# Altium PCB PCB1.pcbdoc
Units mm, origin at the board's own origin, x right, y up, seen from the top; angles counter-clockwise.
Board outline 185.93 x 117.47 mm, 2 copper layers (Top Layer, Bottom Layer); 11 components, 33 nets, 102 pads, 0 vias.
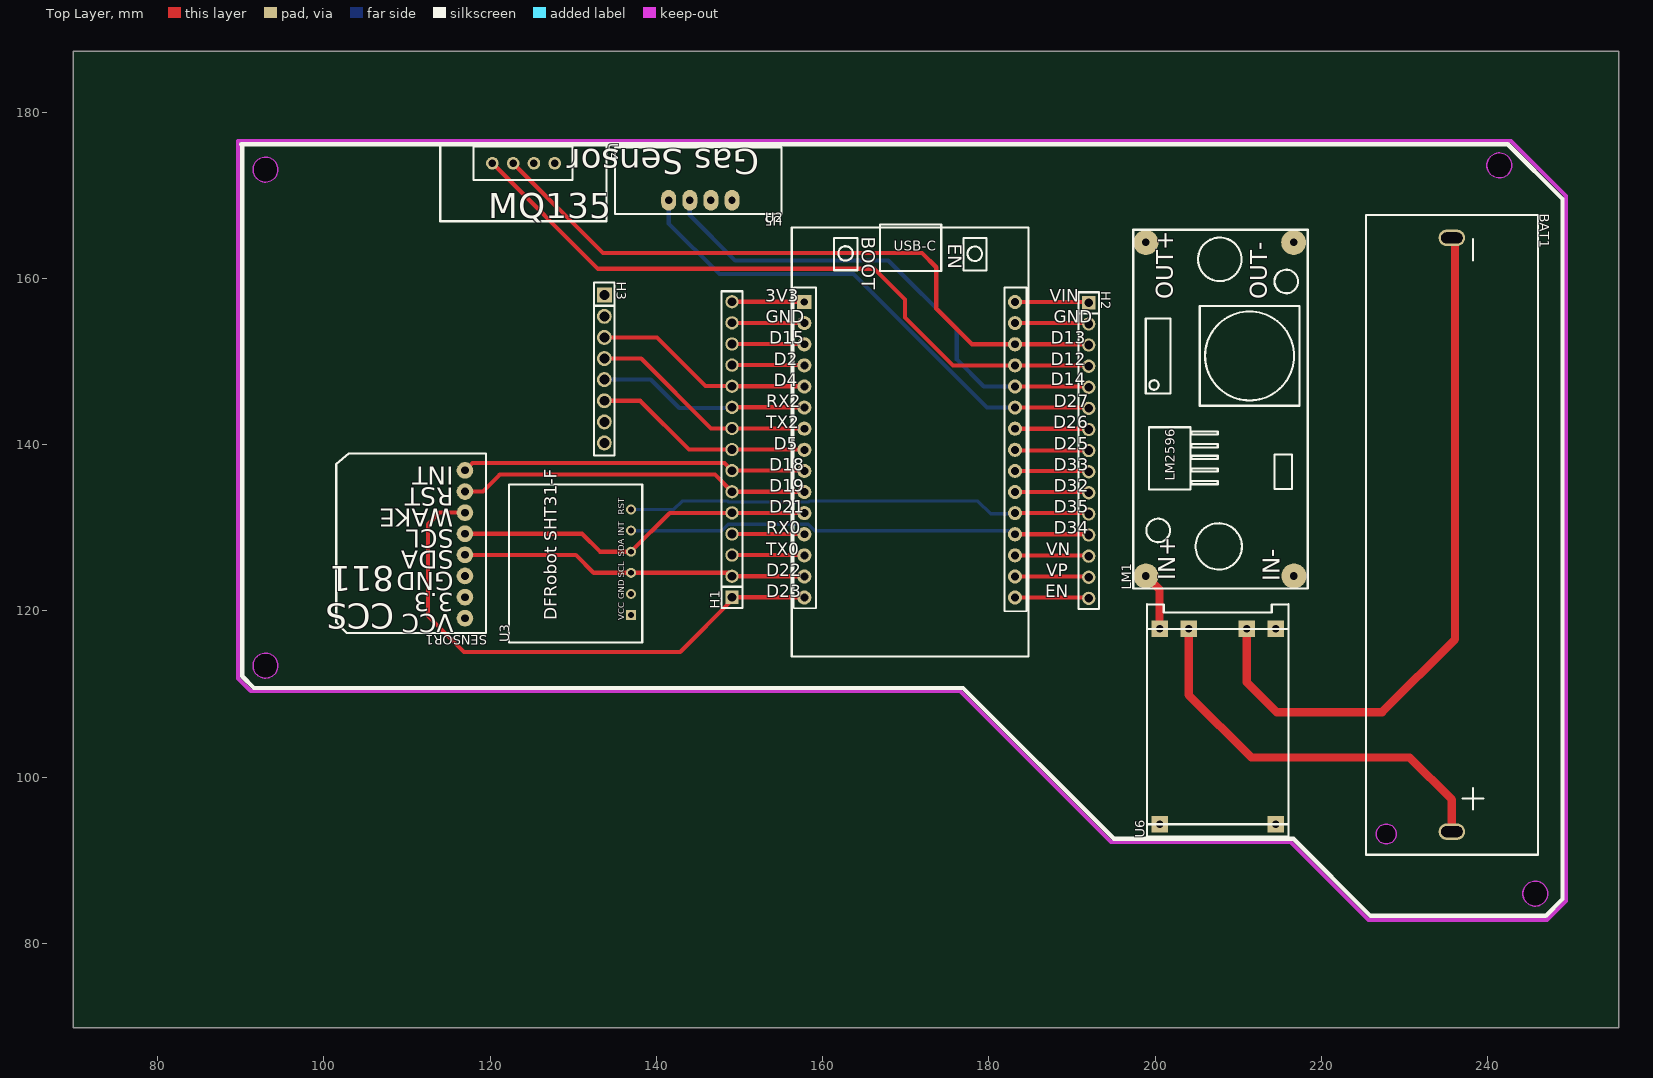
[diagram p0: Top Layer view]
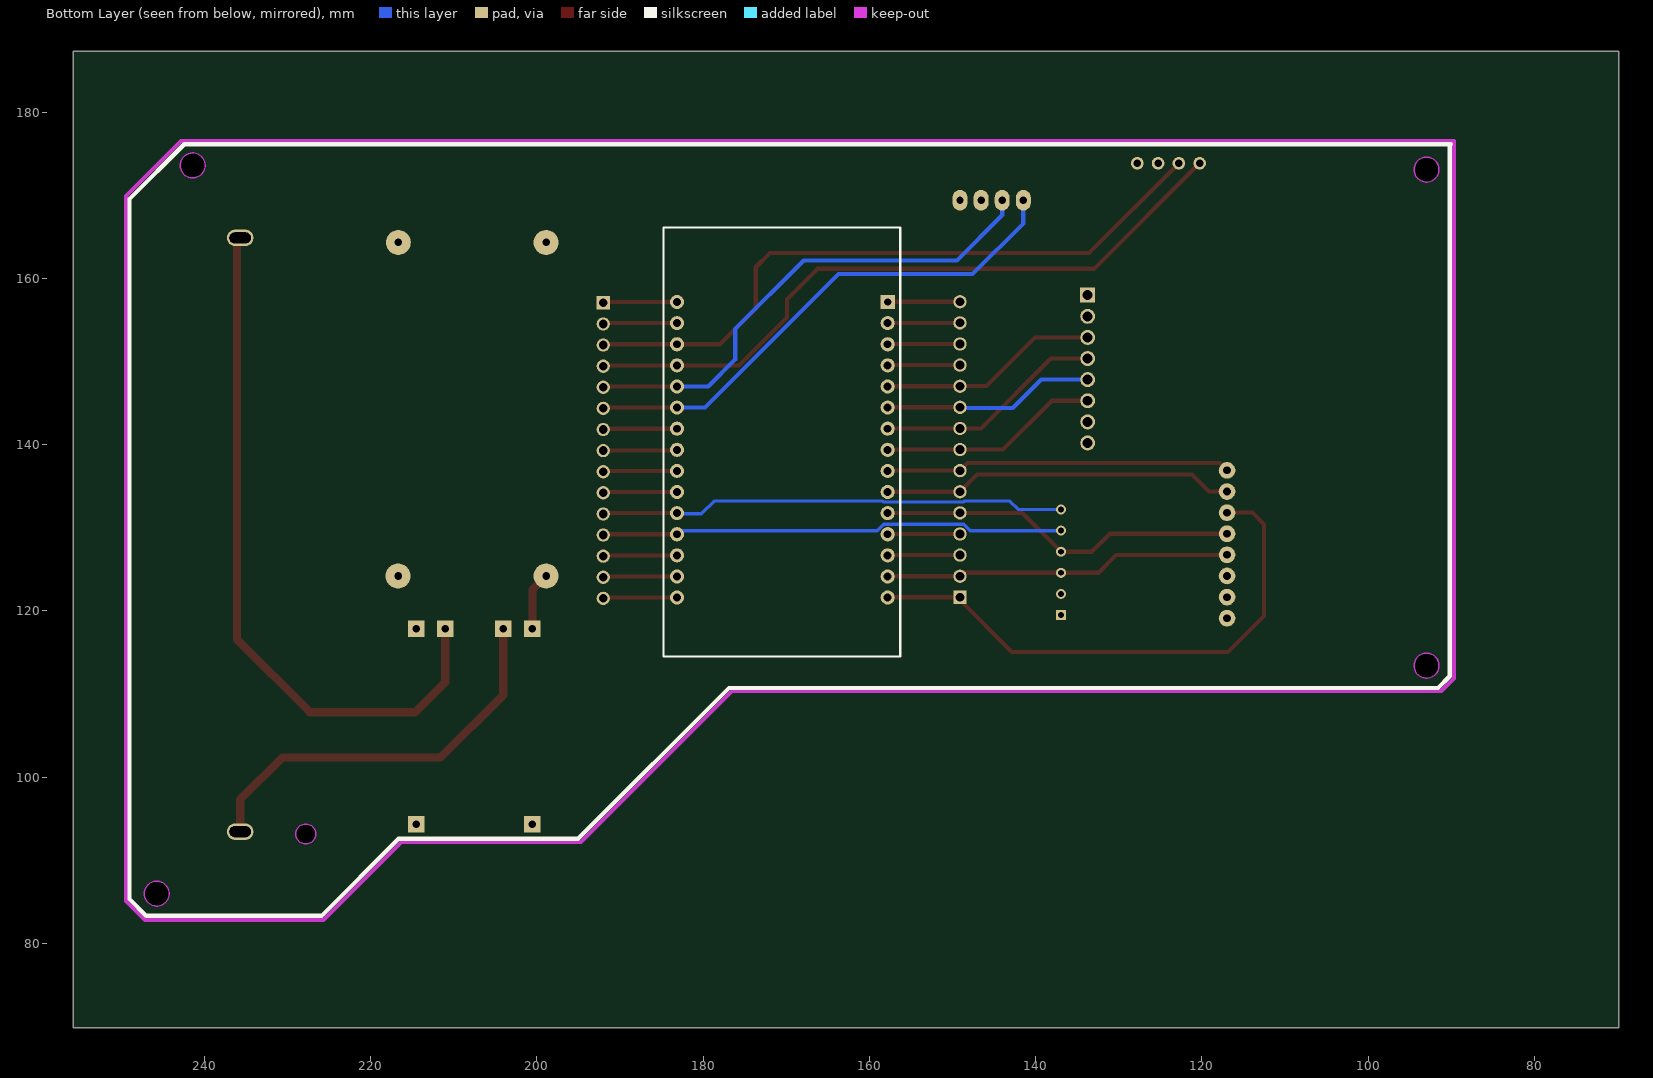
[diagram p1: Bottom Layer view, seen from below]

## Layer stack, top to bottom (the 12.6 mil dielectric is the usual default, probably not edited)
Top Layer: signal copper (thickness not stored)
Dielectric: dielectric 0.32, FR-4, Dk 4.8
Bottom Layer: signal copper (thickness not stored)

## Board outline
255.778,69.85 69.85,69.85 69.85,187.325 255.778,187.325
cut-out: 94.464,173.101 cw(c92.964,173.101) 91.464,173.101 cw(c92.964,173.101)
cut-out: 94.464,113.411 cw(c92.964,113.411) 91.464,113.411 cw(c92.964,113.411)
cut-out: 242.927,173.609 cw(c241.427,173.609) 239.927,173.609 cw(c241.427,173.609)
cut-out: 247.245,85.979 cw(c245.745,85.979) 244.245,85.979 cw(c245.745,85.979)

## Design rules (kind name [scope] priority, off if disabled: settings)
BoardOutlineClearance copperThickness1oz [All] p0: genericclearance=0.254 ignorepadtopadclearanceinfootprint=FALSE except(0: Arc-SplitContinuation Track-SplitContinuation SMDPad-SplitContinuation THPad-SplitContinuation Via-SplitContinuation Fill-SplitContinuation Poly-SplitContinuation Region-SplitContinuation Text-SplitContinuation; 0.152: Track-CutoutEdge SMDPad-CutoutEdge THPad-CutoutEdge Via-CutoutEdge Region-CutoutEdge; 0.3: Track-OutlineEdge SMDPad-OutlineEdge THPad-OutlineEdge Via-OutlineEdge Fill-OutlineEdge Region-OutlineEdge Poly-OutlineEdge Text-OutlineEdge Fill-CutoutEdge)
BoardOutlineClearance copperThickness2oz [All] p0: genericclearance=0.254 ignorepadtopadclearanceinfootprint=FALSE except(0: Arc-SplitContinuation Track-SplitContinuation SMDPad-SplitContinuation THPad-SplitContinuation Via-SplitContinuation Fill-SplitContinuation Poly-SplitContinuation Region-SplitContinuation Text-SplitContinuation; 0.152: Track-CutoutEdge SMDPad-CutoutEdge THPad-CutoutEdge Via-CutoutEdge Region-CutoutEdge; 0.3: Track-OutlineEdge SMDPad-OutlineEdge THPad-OutlineEdge Via-OutlineEdge Fill-OutlineEdge Region-OutlineEdge Poly-OutlineEdge Text-OutlineEdge Fill-CutoutEdge)
Clearance copperThickness1oz [(InNet('$1N893') OR InNet('$1N889') OR InNet('INT_2') OR InNet('SCL') OR InNet('$1N1122') OR InNet('$1N1120') OR InNet('SDA') OR InNet('RST_2') OR InNet('W') OR InNet('RST_1') OR InNet('RX') OR InNet('TX') OR InNet('SET_1') OR InNet('$1N1104') OR InNet('$1N1102') OR InNet('GND') OR InNet('3.3V') OR InNet('$1N1218') OR InNet('$1N1216') OR InNet('D1') OR InNet('A1') OR InNet('D2') OR InNet('A2') OR InNet('$1N1206') OR InNet('$1N1204') OR InNet('$1N1202') OR InNet('$1N1200') OR InNet('RST_3') OR InNet('INT_3') OR InNet('$1N1194') OR InNet('$1N1192') OR InNet('$1N1190') OR InNet('VCC'))] p1: gap=0.178 ignorepadtopadclearanceinfootprint=FALSE except(0.102: Track-Track; 0.152: Track-SMDPad SMDPad-SMDPad Track-THPad SMDPad-THPad THPad-THPad Track-Via SMDPad-Via THPad-Via Via-Via SMDPad-Fill THPad-Fill Via-Fill Fill-Fill Track-Region SMDPad-Region THPad-Region Via-Region Region-Region Track-Poly SMDPad-Poly THPad-Poly Via-Poly Fill-Poly Region-Poly Poly-Poly Track-Text SMDPad-Text THPad-Text Via-Text Fill-Text Region-Text Poly-Text Text-Text; 0.175: Track-Hole SMDPad-Hole THPad-Hole Via-Hole Fill-Hole Region-Hole Poly-Hole Text-Hole Sheet-Hole; 0.3: Track-Fill Fill-Region Track-Sheet SMDPad-Sheet THPad-Sheet Via-Sheet Fill-Sheet Region-Sheet Poly-Sheet Text-Sheet)
Clearance copperThickness2oz [All] p1: gap=0.178 ignorepadtopadclearanceinfootprint=FALSE except(0.152: Track-SMDPad SMDPad-SMDPad Track-THPad SMDPad-THPad THPad-THPad Track-Via SMDPad-Via THPad-Via Via-Via SMDPad-Fill THPad-Fill Via-Fill Fill-Fill Track-Region SMDPad-Region THPad-Region Via-Region Region-Region Track-Poly SMDPad-Poly THPad-Poly Via-Poly Fill-Poly Region-Poly Poly-Poly Track-Text SMDPad-Text THPad-Text Via-Text Fill-Text Region-Text Poly-Text Text-Text; 0.175: Track-Hole SMDPad-Hole THPad-Hole Via-Hole Fill-Hole Region-Hole Poly-Hole Text-Hole Sheet-Hole; 0.203: Track-Track; 0.3: Track-Fill Fill-Region Track-Sheet SMDPad-Sheet THPad-Sheet Via-Sheet Fill-Sheet Region-Sheet Poly-Sheet Text-Sheet)
DiffPairsRouting differentialPair [All] p1: maxuncoupledlength=10 minlimit=6 maxlimit=6 mostfreqgap=6 toplayer_minwidth=5 toplayer_prefwidth=10 toplayer_maxwidth=100 bottomlayer_minwidth=5 bottomlayer_prefwidth=10 bottomlayer_maxwidth=100
PasteMaskExpansion pasteMaskExpansion [All] p1: expansion=0
PlaneConnect innerPlane [All] p1: planeconnectstyle=Relief reliefexpansion=0.508 reliefentries=4 reliefconductorwidth=0.254 reliefairgap=0.254
PolygonConnect copperRegion [All] p1: connectstyle=Direct reliefentries=4 reliefconductorwidth=10 polygonreliefangle="90 Angle" airgapwidth=10
RoutingVias viaSize [All] p1: viastyle="Through Hole" holewidth=12.0078 minholewidth=11.811 maxholewidth=248.0314 width=24.0158 minwidth=19.685 maxwidth=393.7008
SolderMaskExpansion solderMaskExpansion [All] p1: useseparateexpansions=TRUE expansion=2 expansionbottom=2
Width copperThickness1oz [All] p1: maxlimit=100 minlimit=5 preferedwidth=10
Width copperThickness2oz [All] p1: maxlimit=100 minlimit=8 preferedwidth=10

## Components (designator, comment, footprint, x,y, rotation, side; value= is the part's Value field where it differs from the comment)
BAT1 "BH-18650-A6AJ002" BAT-TH_L77.0-W20.7_BH-18650-A6AJ002 235.712,129.159 r270 top
H1 "HDR-M_2.54_1x15P" HDR-TH_15P-P2.54-V-M 149.098,139.418 r90 top
H2 "HDR-M_2.54_1x15P" HDR-TH_15P-P2.54-V-M 192.024,139.291 r270 top
H3 "HDR-F_2.54_1x8P" HDR-TH_8P-P2.54-V-F-1 133.731,149.098 r270 top
LM1 "LM2596" LM2596-STEPDOWN-MODULE 197.376,122.682 r90 top
SENSOR1 "CCS811" CCS811-1 119.507,138.938 r180 top
U2 "ESP32" "ESP32 DOIT DEVKIT V1 mk2" 170.561,139.418 r0 top
U3 "sht31DFBoard" sht31DFBoard 138.557,116.332 r90 top
U4 "MQ135" MQ135 134.112,176.276 r270 top
U5 "gas sensor mq136" "GAS SENSOR" 145.034,175.768 r180 top
U6 "TP4056 Charging Module" "TP4056 Carging Module" 216.045,92.837 r90 top

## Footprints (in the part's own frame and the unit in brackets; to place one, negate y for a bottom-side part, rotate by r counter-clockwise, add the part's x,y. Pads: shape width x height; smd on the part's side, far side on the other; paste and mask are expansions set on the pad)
BAT-TH_L77.0-W20.7_BH-18650-A6AJ002 [mm]
  oval 2x3.2 hole 1.3 slot 2.6 at 90 deg: 1(-35.725,0) 2(35.725,0)
  Board Outline Layer circle w0.005: c36,-7.9 r1.2
  Board Outline Layer region: 36,-6.7 36.52,-6.819 36.938,-7.152 37.17,-7.633 37.17,-8.167 36.938,-8.648 36.52,-8.981 36,-9.1 36,-9.1 35.479,-8.981 35.062,-8.648 34.83,-8.167 34.83,-7.633 35.062,-7.152 35.479,-6.819 36,-6.7
  Multi-Layer board cut-out: 36,-6.7 36.52,-6.819 36.938,-7.152 37.17,-7.633 37.17,-8.167 36.938,-8.648 36.52,-8.981 36,-9.1 36,-9.1 35.479,-8.981 35.062,-8.648 34.83,-8.167 34.83,-7.633 35.062,-7.152 35.479,-6.819 36,-6.7
  silkscreen extent -38.5,-10.35 38.5,10.35
CCS811-1 [mm]
  round 2 hole 0.914: 1(2.54,2.032) 2(2.54,4.572) 3(2.54,7.112) 4(2.54,9.652) 5(2.54,12.192) 6(2.54,14.732) 7(2.54,17.272) 8(2.54,19.812)
  silkscreen extent 0,0 18.03,21.59
"ESP32 DOIT DEVKIT V1 mk2" [mm]
  rect 1.7x1.7 hole 0.889: 1(-12.763,17.755)
  round 1.7 hole 0.95: 4(-12.763,15.215) 6(-12.763,12.668) 7(-12.763,10.128) 8(-12.763,7.588) 9(-12.763,5.048) 10(-12.763,2.508) 11(-12.763,-0.032) 12(-12.763,-2.572) 13(-12.763,-5.112) 14(-12.763,-7.652) 15(-12.763,-10.192) 16(-12.763,-12.732) 17(-12.763,-15.272) 18(-12.763,-17.812) 19(12.586,-17.812) 20(12.586,-15.272) 21(12.586,-12.732) 22(12.586,-10.192) 23(12.586,-7.652) 24(12.586,-5.112) 25(12.586,-2.572) 26(12.586,-0.032) 27(12.586,2.508) 28(12.586,5.048) 29(12.586,7.588) 30(12.586,10.128) 31(12.586,12.668) 35(12.586,15.215) 36(12.586,17.755)
  silkscreen extent -14.27,-24.88 14.23,27.07
"GAS SENSOR" [mm]
  oval 1.8x2.5 hole 0.889: 1(-4.064,6.35) 2(-1.524,6.35) 3(1.016,6.35) 4(3.556,6.35)
  silkscreen extent -10,0 10,8
HDR-TH_8P-P2.54-V-F-1 [mm]
  rect 1.8x1.8 hole 1.2: 1(-8.89,0)
  round 1.8 hole 1.2: 2(-6.35,0) 3(-3.81,0) 4(-1.27,0) 5(1.27,0) 6(3.81,0) 7(6.35,0) 8(8.89,0)
  silkscreen extent -10.41,-1.25 10.41,1.25
HDR-TH_15P-P2.54-V-M [mm]
  rect 1.6x1.6 hole 1.05: 1(-17.78,0)
  round 1.6 hole 1.05: 2(-15.24,0) 3(-12.7,0) 4(-10.16,0) 5(-7.62,0) 6(-5.08,0) 7(-2.54,0) 8(0,0) 9(2.54,0) 10(5.08,0) 11(7.62,0) 12(10.16,0) 13(12.7,0) 14(15.24,0) 15(17.78,0)
  silkscreen extent -19.05,-1.25 19.05,1.25
LM2596-STEPDOWN-MODULE [mil]
  round 118.11 hole 36: 1(60,-60) 2(60,-761.26) 3(1640,-60) 4(1640,-760)
  silkscreen extent 0,-827 1700,0
MQ135 [mil]
  round 60 hole 36: 1(95,-250) 2(95,-348.43) 3(95,-446.85) 4(95,-545.28)
  silkscreen extent 5,-792 370,-5
sht31DFBoard [mm]
  round 1.2 hole 0.7: 1(15.874,1.621) 2(13.334,1.621) 3(10.794,1.621) 4(8.254,1.621) 5(5.714,1.621)
  rect 1.2x1.2 hole 0.7: 6(3.174,1.621)
  silkscreen extent -0.13,0.25 18.9,16.28
"TP4056 Carging Module" [mm]
  rect 2x2 hole 0.914: 1(1.5,15.5) 2(1.5,1.5) 3(25,15.5) 4(25,12) 5(25,5) 6(25,1.5)
  silkscreen extent 0,0 28,17

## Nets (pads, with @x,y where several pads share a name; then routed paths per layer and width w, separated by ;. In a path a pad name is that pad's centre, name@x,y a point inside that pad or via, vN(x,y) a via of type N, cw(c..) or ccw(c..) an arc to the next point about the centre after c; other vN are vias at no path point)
3.3V: H1.15 H3.1 LM1.3 SENSOR1.7 SENSOR1.8 U2.1 U3.6 U4.1 U5.1 | length 8.7
  Top Layer w0.5: H1.15 157.772,157.198 U2.1
$1N889: BAT1.2 U6.4 | length 48.7
  Top Layer w1: U6.4 204.045,109.899 211.582,102.362 230.632,102.362 235.712,97.282 BAT1.2
$1N893: BAT1.1 U6.5 | length 85
  Top Layer w1: U6.5 211.045,111.408 214.63,107.823 227.33,107.823 236.093,116.586 236.093,164.503 BAT1.1
$1N1102: H1.13 U2.6 | length 8.7
  Top Layer w0.5: H1.13 157.765,152.118 U2.6
$1N1104: H1.12 U2.7 | length 8.7
  Top Layer w0.5: H1.12 157.765,149.578 U2.7
$1N1120: H1.4 U2.15 | length 8.7
  Top Layer w0.5: H1.4 157.765,129.258 U2.15
$1N1122: H1.3 U2.16 | length 8.7
  Top Layer w0.5: H1.3 157.765,126.718 U2.16
$1N1190: H2.15 U2.19 | length 8.9
  Top Layer w0.5: U2.19 191.929,121.606 H2.15
$1N1192: H2.14 U2.20 | length 8.9
  Top Layer w0.5: U2.20 191.929,124.146 H2.14
$1N1194: H2.13 U2.21 | length 8.9
  Top Layer w0.5: U2.21 191.929,126.686 H2.13
$1N1200: H2.10 U2.24 | length 8.9
  Top Layer w0.5: U2.24 191.929,134.306 H2.10
$1N1202: H2.9 U2.25 | length 8.9
  Top Layer w0.5: U2.25 191.929,136.846 H2.9
$1N1204: H2.8 U2.26 | length 8.9
  Top Layer w0.5: U2.26 183.242,139.291 H2.8
$1N1206: H2.7 U2.27 | length 8.9
  Top Layer w0.5: U2.27 191.929,141.926 H2.7
$1N1216: H2.2 U2.35 | length 8.9
  Top Layer w0.5: U2.35 191.922,154.633 H2.2
$1N1218: H2.1 U2.36 | length 8.9
  Top Layer w0.5: U2.36 191.922,157.173 H2.1
A1: H2.4 U2.30 U4.4 | length 83.1
  Top Layer w0.5: U4.4 132.962,161.163 166.243,161.163 169.926,157.48 169.926,155.321 175.701,149.546 U2.30 191.929,149.546 H2.4
A2: H2.6 U2.28 U5.4 | length 62.6
  Top Layer w0.5: U2.28 191.929,144.466 H2.6
  Bottom Layer w0.5: U5.4 141.478,166.624 147.574,160.528 163.703,160.528 179.765,144.466 U2.28
D1: H2.3 U2.31 U4.3 | length 81.2
  Top Layer w0.5: U4.3 133.557,163.068 171.958,163.068 173.672,161.353 173.672,156.4 177.987,152.086 U2.31 191.929,152.086 H2.3
D2: H2.5 U2.29 U5.3 | length 60.5
  Top Layer w0.5: U2.29 191.929,147.006 H2.5
  Bottom Layer w0.5: U5.3 144.018,167.64 149.479,162.179 167.894,162.179 176.149,153.924 176.149,150.241 179.384,147.006 U2.29
GND: H1.14 H3.2 LM1.2 LM1.4 SENSOR1.6 U2.4 U3.5 U4.2 U5.2 U6.6 | length 8.7
  Top Layer w0.5: H1.14 157.772,154.658 U2.4
INT_2: H1.1 SENSOR1.3 U2.18 | length 65.9
  Top Layer w0.5: SENSOR1.3 113.919,131.826 112.522,130.429 112.522,119.38 116.84,115.062 142.875,115.062 H1.1@149.225,121.412 ; H1.1 157.765,121.638 U2.18
INT_3: H2.12 U2.22 U3.2 | length 55.9
  Top Layer w0.5: U2.22 191.929,129.226 H2.12
  Bottom Layer w0.4: U3.2 147.877,129.666 148.639,130.428 158.295,130.428 159.057,129.666 182.707,129.666 U2.22
RST_1: H1.8 H3.6 U2.11 | length 26.5
  Top Layer w0.5: H3.6 138.049,145.288 143.919,139.418 H1.8 157.765,139.418 U2.11
RST_2: H1.6 SENSOR1.2 U2.13 | length 42.5
  Top Layer w0.5: SENSOR1.2 119.126,134.366 121.158,136.398 147.038,136.398 H1.6 157.765,134.338 U2.13
RST_3: H2.11 U2.23 U3.1 | length 56.3
  Top Layer w0.5: U2.23 191.929,131.766 H2.11
  Bottom Layer w0.4: U3.1 142.112,132.206 143.129,133.223 148.584,133.223 148.703,133.104 158.295,133.104 158.414,133.223 178.689,133.223 180.213,131.699 183.08,131.699 U2.23
RX: H1.9 H3.4 U2.10 | length 27.6
  Top Layer w0.5: H3.4 138.176,150.368 146.586,141.958 H1.9 157.765,141.958 U2.10
SCL: H1.2 SENSOR1.5 U2.17 U3.4 | length 41.9
  Top Layer w0.5: SENSOR1.5 130.302,126.746 132.462,124.586 U3.4 148.69,124.586 H1.2 157.765,124.178 U2.17
SDA: H1.5 SENSOR1.4 U2.14 U3.3 | length 43.7
  Top Layer w0.5: SENSOR1.4 131.064,129.286 133.223,127.127 U3.3@136.935,127.127 ; U3.3 141.608,131.798 H1.5 157.765,131.798 U2.14
SET_1: H1.11 H3.3 U2.8 | length 26.5
  Top Layer w0.5: H3.3 140.081,152.908 145.923,147.066 149.07,147.066 H1.11 157.765,147.038 U2.8
TX: H1.10 H3.5 U2.9 | length 25.5
  Top Layer w0.5: H1.10 157.765,144.498 U2.9
  Bottom Layer w0.5: H3.5 139.319,147.828 142.748,144.399 148.999,144.399 H1.10
VCC: LM1.1 U6.3 | length 7.1
  Top Layer w1: LM1.1 200.545,122.561 U6.3
W: H1.7 SENSOR1.1 U2.12 | length 41.6
  Top Layer w0.5: SENSOR1.1 117.856,137.795 148.181,137.795 H1.7 157.765,136.878 U2.12
pads on no net: H3.7 H3.8 U6.1 U6.2

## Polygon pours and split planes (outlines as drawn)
GND on Bottom Layer (solid, remove dead copper, pour order 2): 76.2,180.594 220.218,180.594 220.218,76.2 76.2,76.2
3.3V on Top Layer (solid, remove dead copper, pour order 0): 81.153,180.975 220.218,180.975 220.218,79.248 81.153,79.248

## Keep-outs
Board Outline Layer:
  circle w0.025: c92.964,173.101 r1.5
  region: 94.464,173.101 cw(c92.964,173.101) 91.464,173.101 cw(c92.964,173.101)
  circle w0.025: c92.964,113.411 r1.5
  region: 94.464,113.411 cw(c92.964,113.411) 91.464,113.411 cw(c92.964,113.411)
  circle w0.025: c241.427,173.609 r1.5
  region: 242.927,173.609 cw(c241.427,173.609) 239.927,173.609 cw(c241.427,173.609)
  circle w0.025: c245.745,85.979 r1.5
  region: 247.245,85.979 cw(c245.745,85.979) 244.245,85.979 cw(c245.745,85.979)
  lines w0.5: 89.662,111.887 91.186,110.363 176.53,110.363 194.691,92.202 216.281,92.202 225.679,82.804 247.142,82.804 249.428,85.09 249.428,169.926 242.824,176.53 89.662,176.53 89.662,111.887

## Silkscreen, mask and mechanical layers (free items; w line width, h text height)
Top Silkscreen Layer:
  lines w0.5: 90.043,176.149 242.443,176.149 249.047,169.545 249.047,85.344 247.015,83.312 225.933,83.312 216.662,92.583 195.072,92.583 176.911,110.744 91.567,110.744 90.17,112.141 90.17,176.022 90.043,176.149
Bottom Silkscreen Layer:
  lines w0.5: 90.043,176.149 242.443,176.149 249.047,169.545 249.047,85.344 247.015,83.312 225.933,83.312 216.662,92.583 195.072,92.583 176.911,110.744 91.567,110.744 90.17,112.141 90.17,176.022 90.043,176.149
Mechanical Layer:
  circle w0.025: c92.964,173.101 r1.5
  circle w0.025: c92.964,113.411 r1.5
  circle w0.025: c241.427,173.609 r1.5
  circle w0.025: c245.745,85.979 r1.5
